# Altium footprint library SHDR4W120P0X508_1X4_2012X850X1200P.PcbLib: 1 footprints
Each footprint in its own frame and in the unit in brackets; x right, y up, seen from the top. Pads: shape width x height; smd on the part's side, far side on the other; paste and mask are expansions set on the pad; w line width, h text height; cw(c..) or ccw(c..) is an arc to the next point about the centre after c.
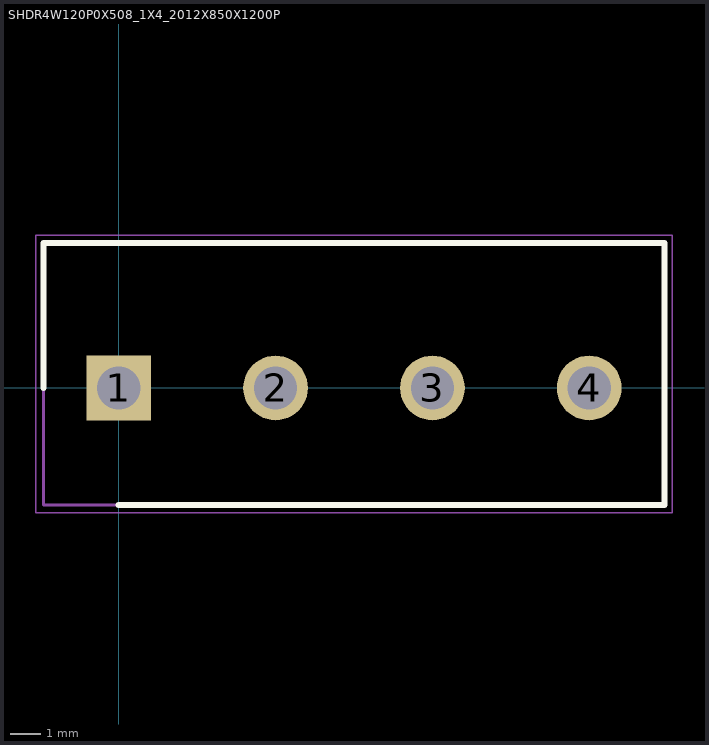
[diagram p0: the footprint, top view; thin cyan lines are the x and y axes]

## SHDR4W120P0X508_1X4_2012X850X1200P [mm]
pads (4):
  rect 2.1x2.1 / inner round 2.1 / far side rect 2.1x2.1 hole 1.4: 1(0,0)
  round 2.1 hole 1.4: 2(5.08,0) 3(10.16,0) 4(15.24,0)
Top Overlay:
  lines w0.2: -2.44,0 -2.44,4.7 17.68,4.7 17.68,-3.8 0,-3.8
Mechanical 15:
  lines w0.1: -2.44,-3.8 -2.44,4.7 17.68,4.7 17.68,-3.8 -2.44,-3.8
Mechanical 20:
  lines w0.05: -2.69,-4.05 -2.69,4.95 17.93,4.95 17.93,-4.05 -2.69,-4.05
